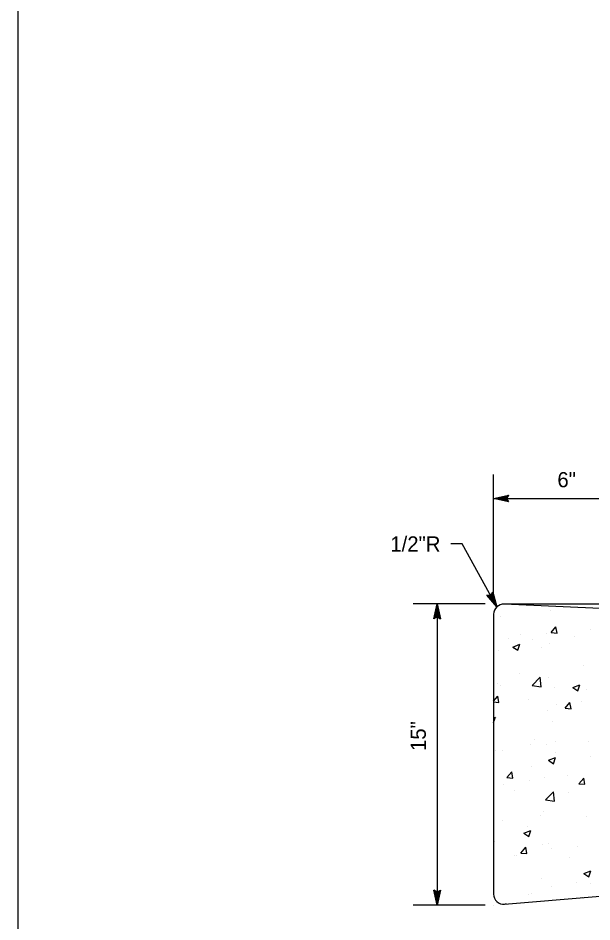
# Model space of a CAD drawing. Extents: x -119017 to -116080, y -104449 to -102845.
# Drawn here: x -119016.8 to -118790, y -103990.3 to -103633 of the extents above; entities that cross this region are included whole.
import ezdxf

# ---------------------------------------------------------------- set-up
doc = ezdxf.new("R2010")
doc.units = 0
for name, color, linetype in [('Default', 7, 'Continuous'), ('G-MARK', 7, 'Continuous'), ('G-TEXT', 7, 'Continuous'), ('Misc CnstDet(22)', 7, 'Continuous')]:
    doc.layers.add(name, color=color, linetype=linetype)

msp = doc.modelspace()

# ---------------------------------------------------------------- linework, layer by layer
at = {"layer": 'Default'}
msp.add_lwpolyline([(-119016.83, -102845.16), (-117223.08, -102845.16), (-117223.08, -104295.16), (-119016.83, -104295.16)], close=True, dxfattribs=at)
at = {"layer": 'G-MARK'}
for p, q in [((-118828.88, -103861.15), (-118828.88, -103813.36)), ((-118828.88, -103822.9), (-118781.19, -103822.9)), ((-118832.23, -103864.49), (-118860.75, -103864.49)), ((-118851.21, -103864.49), (-118851.21, -103983.63)), ((-118825.53, -103864.49), (-118673.4, -103864.49)), ((-118832.23, -103983.63), (-118860.75, -103983.63))]:
    msp.add_line(p, q, dxfattribs=at)
msp.add_lwpolyline([(-118827.66, -103865.77), (-118841.3, -103840.79), (-118845.77, -103840.79)], dxfattribs=at)
at = {"layer": 'G-TEXT'}
for points in [[(-118822.98, -103824.22), (-118828.88, -103822.9), (-118822.97, -103821.59), (-118823.18, -103821.94), (-118827.51, -103822.9), (-118823.18, -103823.87), (-118823.39, -103823.52), (-118826.16, -103822.9), (-118823.39, -103822.29), (-118823.61, -103822.64), (-118824.8, -103822.9), (-118823.6, -103823.17), (-118823.76, -103822.9), (-118822.97, -103821.59), (-118823.76, -103822.9)], [(-118829.24, -103859.93), (-118827.66, -103865.77), (-118831.56, -103861.15), (-118831.16, -103861.18), (-118828.3, -103864.56), (-118829.45, -103860.28), (-118829.66, -103860.62), (-118828.92, -103863.36), (-118830.75, -103861.2), (-118830.34, -103861.22), (-118829.55, -103862.16), (-118829.87, -103860.97), (-118830.04, -103861.24), (-118831.56, -103861.15), (-118830.04, -103861.24)], [(-118852.53, -103870.4), (-118851.21, -103864.49), (-118849.9, -103870.4), (-118850.25, -103870.19), (-118851.2, -103865.86), (-118852.18, -103870.19), (-118851.83, -103869.98), (-118851.21, -103867.21), (-118850.6, -103869.98), (-118850.95, -103869.77), (-118851.21, -103868.57), (-118851.48, -103869.77), (-118851.21, -103869.61), (-118849.9, -103870.4), (-118851.21, -103869.61)], [(-118849.89, -103977.73), (-118851.21, -103983.63), (-118852.52, -103977.73), (-118852.17, -103977.94), (-118851.21, -103982.27), (-118850.24, -103977.94), (-118850.59, -103978.15), (-118851.21, -103980.92), (-118851.82, -103978.15), (-118851.47, -103978.36), (-118851.21, -103979.56), (-118850.94, -103978.35), (-118851.21, -103978.52), (-118852.52, -103977.73), (-118851.21, -103978.52)]]:
    msp.add_lwpolyline(points, close=True, dxfattribs=at)
at = {"layer": 'Misc CnstDet(22)'}
for p, q in [((-118828.88, -103864.49), (-118828.88, -103864.49)), ((-118828.88, -103864.49), (-118828.88, -103864.49)), ((-118828.88, -103864.49), (-118828.88, -103864.49)), ((-118806.24, -103867.18), (-118806.24, -103867.18)), ((-118826.32, -103869.71), (-118826.32, -103869.71)), ((-118806.18, -103875.91), (-118804.27, -103873.62)), ((-118803.83, -103876.12), (-118804.27, -103873.62)), ((-118790.45, -103874.56), (-118790.45, -103874.56)), ((-118823.19, -103878.41), (-118823.19, -103878.41)), ((-118818.31, -103876.62), (-118818.31, -103876.62)), ((-118813.62, -103878.53), (-118813.62, -103878.53)), ((-118808.15, -103876.41), (-118808.15, -103876.41)), ((-118806.18, -103875.91), (-118803.83, -103876.12)), ((-118797.11, -103877.5), (-118797.11, -103877.5)), ((-118821.28, -103881.6), (-118818.5, -103880.53)), ((-118821.28, -103881.6), (-118819.31, -103882.91)), ((-118819.31, -103882.91), (-118818.5, -103880.53)), ((-118809.93, -103881.94), (-118809.93, -103881.94)), ((-118806.74, -103880.41), (-118806.74, -103880.41)), ((-118826.79, -103882.94), (-118826.79, -103882.94)), ((-118793.51, -103888.79), (-118793.51, -103888.79)), ((-118818.59, -103892.07), (-118818.59, -103892.07)), ((-118827.29, -103896.17), (-118827.29, -103896.17)), ((-118813.62, -103896.76), (-118810.52, -103893.54)), ((-118810.09, -103897.33), (-118810.52, -103893.54)), ((-118807.21, -103893.64), (-118807.21, -103893.64)), ((-118797.58, -103897.58), (-118794.8, -103896.51)), ((-118795.61, -103898.92), (-118794.8, -103896.51)), ((-118826.22, -103896.79), (-118826.22, -103896.79)), ((-118813.62, -103896.76), (-118810.09, -103897.33)), ((-118805.02, -103897.7), (-118805.02, -103897.7)), ((-118797.58, -103897.58), (-118795.61, -103898.92)), ((-118792.11, -103898.26), (-118792.11, -103898.26)), ((-118828.88, -103902.95), (-118827.25, -103901.02)), ((-118828.88, -103903.33), (-118826.79, -103903.49)), ((-118826.79, -103903.49), (-118827.25, -103901.02)), ((-118815.25, -103902.24), (-118815.25, -103902.24)), ((-118800.67, -103905.77), (-118798.77, -103903.49)), ((-118798.3, -103905.99), (-118798.77, -103903.49)), ((-118794.01, -103903.14), (-118794.01, -103903.14)), ((-118807.71, -103906.83), (-118807.71, -103906.83)), ((-118803.96, -103904.42), (-118803.96, -103904.42)), ((-118800.67, -103905.77), (-118798.3, -103905.99)), ((-118828.88, -103911.43), (-118828.16, -103909.33)), ((-118828.88, -103909.58), (-118828.16, -103909.33)), ((-118827.75, -103909.4), (-118827.75, -103909.4)), ((-118805.74, -103910.96), (-118805.74, -103910.96)), ((-118812.74, -103918), (-118812.74, -103918)), ((-118814.4, -103920.09), (-118814.4, -103920.09)), ((-118808.18, -103920.06), (-118808.18, -103920.06)), ((-118804.46, -103918.78), (-118804.46, -103918.78)), ((-118791.54, -103918.87), (-118791.54, -103918.87)), ((-118828.22, -103922.59), (-118828.22, -103922.59)), ((-118825.57, -103922.44), (-118825.57, -103922.44)), ((-118804.36, -103923.31), (-118804.36, -103923.31)), ((-118790.57, -103924.84), (-118790.57, -103924.84)), ((-118807.24, -103926.38), (-118804.46, -103925.31)), ((-118807.24, -103926.38), (-118805.27, -103927.72)), ((-118805.27, -103927.72), (-118804.46, -103925.31)), ((-118823.66, -103933.16), (-118821.75, -103930.88)), ((-118821.28, -103933.38), (-118821.75, -103930.88)), ((-118813.75, -103928.85), (-118813.75, -103928.85)), ((-118828.72, -103935.82), (-118828.72, -103935.82)), ((-118824.85, -103935.76), (-118824.85, -103935.76)), ((-118823.66, -103933.16), (-118821.28, -103933.38)), ((-118814.9, -103934.44), (-118814.9, -103934.44)), ((-118808.65, -103933.29), (-118808.65, -103933.29)), ((-118799.86, -103932.47), (-118799.86, -103932.47)), ((-118795.17, -103935.66), (-118793.26, -103933.38)), ((-118795.17, -103935.66), (-118792.79, -103935.85)), ((-118792.79, -103935.85), (-118793.26, -103933.38)), ((-118820.66, -103938.17), (-118820.66, -103938.17)), ((-118808.34, -103942.04), (-118805.24, -103938.79)), ((-118804.8, -103942.58), (-118805.24, -103938.82)), ((-118799.45, -103939.07), (-118799.45, -103939.07)), ((-118808.34, -103942.04), (-118804.8, -103942.58)), ((-118809.15, -103946.52), (-118809.15, -103946.52)), ((-118825.35, -103950.11), (-118825.35, -103950.11)), ((-118810.31, -103948.14), (-118810.31, -103948.14)), ((-118792.2, -103948.55), (-118792.2, -103948.55)), ((-118815.37, -103952.52), (-118815.37, -103952.52)), ((-118816.9, -103955.18), (-118814.12, -103954.11)), ((-118816.9, -103955.18), (-118814.93, -103956.52)), ((-118814.93, -103956.52), (-118814.12, -103954.11)), ((-118828.38, -103958.46), (-118828.38, -103958.46)), ((-118818.15, -103963.03), (-118816.22, -103960.74)), ((-118815.78, -103963.25), (-118816.22, -103960.74)), ((-118809.62, -103959.71), (-118809.62, -103959.71)), ((-118807.18, -103959.37), (-118807.18, -103959.37)), ((-118795.67, -103960.49), (-118795.67, -103960.49)), ((-118820.75, -103963.81), (-118820.75, -103963.81)), ((-118820, -103963.81), (-118820, -103963.81)), ((-118818.15, -103963.03), (-118815.78, -103963.25)), ((-118805.87, -103961.24), (-118805.87, -103961.24)), ((-118798.8, -103964.68), (-118798.8, -103964.68)), ((-118793.2, -103971.16), (-118790.42, -103970.09)), ((-118793.2, -103971.16), (-118791.23, -103972.5)), ((-118791.23, -103972.5), (-118790.42, -103970.09)), ((-118810.12, -103972.94), (-118810.12, -103972.94)), ((-118796.2, -103974.85), (-118796.2, -103974.85)), ((-118790.7, -103975.16), (-118790.7, -103975.16)), ((-118806.12, -103976.16), (-118806.12, -103976.16)), ((-118815.09, -103979.54), (-118815.09, -103979.54)), ((-118813.84, -103979.13), (-118813.84, -103979.13)), ((-118793.89, -103980.44), (-118793.89, -103980.44)), ((-118851.21, -103983.63), (-118851.21, -103983.63)), ((-118828.88, -103983.63), (-118828.88, -103983.63)), ((-118824.75, -103983.29), (-118823.78, -103982.92)), ((-118823.88, -103983.2), (-118823.78, -103982.92))]:
    msp.add_line(p, q, dxfattribs=at)
for points in [[(-118783.91, -103866.52), (-118824.72, -103864.68)], [(-118828.88, -103868.65), (-118828.88, -103979.32)], [(-118824.57, -103983.26), (-118641.85, -103968)]]:
    msp.add_lwpolyline(points, dxfattribs=at)
for centre, start, end in [((-118824.91, -103868.64), 87.3974, 180), ((-118824.91, -103979.31), 180, 274.7742)]:
    msp.add_arc(centre, 3.97, start, end, dxfattribs=at)

# ---------------------------------------------------------------- texts
for s, p in [('6"', (-118803.69, -103818.47)), ('1/2"R', (-118869.7, -103843.87))]:
    msp.add_text(s, height=6, dxfattribs=at).set_placement(p)
msp.add_text('15"', height=6, rotation=90, dxfattribs=at).set_placement((-118855.67, -103922.7))

doc.saveas('drawing.dxf')
